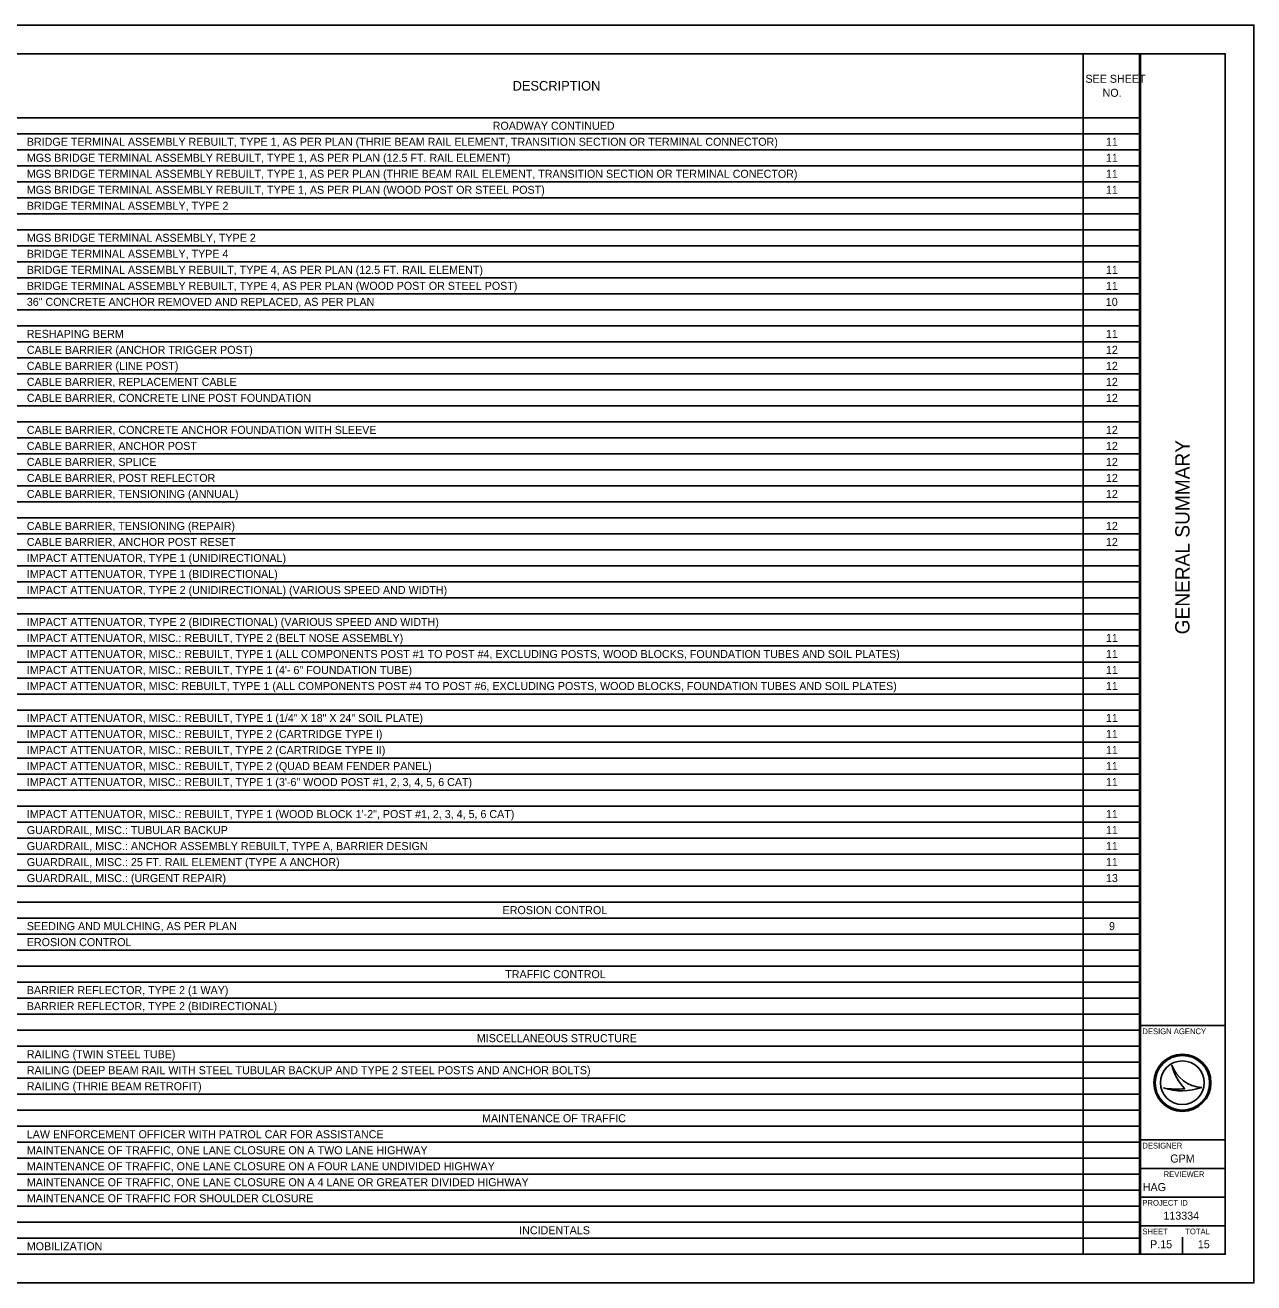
# Model space of a CAD drawing. Extents: x 0 to 34, y 0 to 22.
# Drawn here: x 12.51 to 34, y 0 to 22 of the extents above; entities that cross this region are included whole.
import ezdxf

# ---------------------------------------------------------------- set-up
doc = ezdxf.new("R2010")
doc.units = 0
for name, color, linetype in [('Default', 7, 'Continuous'), ('SH_Border', 7, 'Continuous'), ('SH_Cut_Line', 7, 'Continuous'), ('SH_Data', 7, 'Continuous')]:
    doc.layers.add(name, color=color, linetype=linetype)

msp = doc.modelspace()

# ---------------------------------------------------------------- linework, layer by layer
at = {"layer": 'Default'}
for p, q in [((1.5, 21.5), (32.02, 21.5)), ((31.015, 21.5), (31.015, 0.5)), ((32.02, 21.5), (32.02, 0.5)), ((1.5, 20.38), (32.02, 20.38)), ((1.5, 20.1), (32.02, 20.1)), ((1.5, 19.82), (32.02, 19.82)), ((1.5, 19.54), (32.02, 19.54)), ((1.5, 19.26), (32.02, 19.26)), ((1.5, 18.98), (32.02, 18.98)), ((1.5, 18.7), (32.02, 18.7)), ((1.5, 18.42), (32.02, 18.42)), ((1.5, 18.14), (32.02, 18.14)), ((1.5, 17.86), (32.02, 17.86)), ((1.5, 17.58), (32.02, 17.58)), ((1.5, 17.3), (32.02, 17.3)), ((1.5, 17.02), (32.02, 17.02)), ((1.5, 16.74), (32.02, 16.74)), ((1.5, 16.46), (32.02, 16.46)), ((1.5, 16.18), (32.02, 16.18)), ((1.5, 15.9), (32.02, 15.9)), ((1.5, 15.62), (32.02, 15.62)), ((1.5, 15.34), (32.02, 15.34)), ((1.5, 15.06), (32.02, 15.06)), ((1.5, 14.78), (32.02, 14.78)), ((1.5, 14.5), (32.02, 14.5)), ((1.5, 14.22), (32.02, 14.22)), ((1.5, 13.94), (32.02, 13.94)), ((1.5, 13.66), (32.02, 13.66)), ((1.5, 13.38), (32.02, 13.38)), ((1.5, 13.1), (32.02, 13.1)), ((1.5, 12.82), (32.02, 12.82)), ((1.5, 12.54), (32.02, 12.54)), ((1.5, 12.26), (32.02, 12.26)), ((1.5, 11.98), (32.02, 11.98)), ((1.5, 11.7), (32.02, 11.7)), ((1.5, 11.42), (32.02, 11.42)), ((1.5, 11.14), (32.02, 11.14)), ((1.5, 10.86), (32.02, 10.86)), ((1.5, 10.58), (32.02, 10.58)), ((1.5, 10.3), (32.02, 10.3)), ((1.5, 10.02), (32.02, 10.02)), ((1.5, 9.74), (32.02, 9.74)), ((1.5, 9.46), (32.02, 9.46)), ((1.5, 9.18), (32.02, 9.18)), ((1.5, 8.9), (32.02, 8.9)), ((1.5, 8.62), (32.02, 8.62)), ((1.5, 8.34), (32.02, 8.34)), ((1.5, 8.06), (32.02, 8.06)), ((1.5, 7.78), (32.02, 7.78)), ((1.5, 7.5), (32.02, 7.5)), ((1.5, 7.22), (32.02, 7.22)), ((1.5, 6.94), (32.02, 6.94)), ((1.5, 6.66), (32.02, 6.66)), ((1.5, 6.38), (32.02, 6.38)), ((1.5, 6.1), (32.02, 6.1)), ((1.5, 5.82), (32.02, 5.82)), ((1.5, 5.54), (32.02, 5.54)), ((1.5, 5.26), (32.02, 5.26)), ((1.5, 4.98), (32.02, 4.98)), ((1.5, 4.7), (32.02, 4.7)), ((1.5, 4.42), (32.02, 4.42)), ((1.5, 4.14), (32.02, 4.14)), ((1.5, 3.86), (32.02, 3.86)), ((1.5, 3.58), (32.02, 3.58)), ((1.5, 3.3), (32.02, 3.3)), ((1.5, 3.02), (32.02, 3.02)), ((1.5, 2.74), (32.02, 2.74)), ((1.5, 2.46), (32.02, 2.46)), ((1.5, 2.18), (32.02, 2.18)), ((1.5, 1.9), (32.02, 1.9)), ((1.5, 1.62), (32.02, 1.62)), ((1.5, 1.34), (32.02, 1.34)), ((1.5, 1.06), (32.02, 1.06)), ((1.5, 0.78), (32.02, 0.78)), ((1.5, 0.5), (32.02, 0.5))]:
    msp.add_line(p, q, dxfattribs=at)
at = {"layer": 'SH_Border'}
for p, q in [((32, 0.5), (32, 21.5)), ((32, 4.5), (33.5, 4.5)), ((32, 2.5), (33.5, 2.5)), ((32, 2), (33.5, 2)), ((32, 1.5), (33.5, 1.5)), ((32, 1), (33.5, 1))]:
    msp.add_line(p, q, dxfattribs=at)
msp.add_lwpolyline([(1.5, 21.5), (33.5, 21.5), (33.5, 0.5), (1.5, 0.5)], close=True, dxfattribs=at)
at = {"layer": 'SH_Cut_Line'}
msp.add_lwpolyline([(0, 0), (34, 0), (34, 22), (0, 22)], close=True, dxfattribs=at)
at = {"layer": 'SH_Data'}
for p, q in [((32.567, 3.81), (32.567, 3.81)), ((32.417, 3.41), (32.417, 3.41)), ((32.75, 3.5), (32.75, 3.5)), ((33.087, 3.419), (33.087, 3.419)), ((32.375, 0.675), (32.375, 0.675)), ((32.75, 0.5), (32.75, 0.8))]:
    msp.add_line(p, q, dxfattribs=at)
for radius in [0.5, 0.477, 0.477, 0.382]:
    msp.add_circle((32.75, 3.5), radius, dxfattribs=at)
for centre, radius, start, end in [((33.116, 3.998), 0.58, 198.9257, 198.9319), ((33.347, 3.97), 0.796, 191.6379, 191.6421), ((33.116, 3.998), 0.58, 198.9319, 267.1657), ((33.347, 3.97), 0.796, 191.6421, 226.0947), ((32.739, 4.37), 1.013, 251.4576, 290.0832), ((32.648, 4.654), 1.266, 259.4964, 259.4995), ((32.739, 4.37), 1.013, 251.4527, 251.4576), ((32.648, 4.654), 1.266, 259.4995, 276.6672)]:
    msp.add_arc(centre, radius, start, end, dxfattribs=at)

# ---------------------------------------------------------------- texts
at = {"layer": 'Default'}
for s, height, p in [('SEE SHEET ', 0.14, (31.054, 20.992)), ('DESCRIPTION', 0.168, (21.033, 20.856)), ('NO.', 0.14, (31.354, 20.747)), ('ROADWAY CONTINUED', 0.14, (20.685, 20.17)), ('BRIDGE TERMINAL ASSEMBLY REBUILT, TYPE 1, AS PER PLAN (THRIE BEAM RAIL ELEMENT, TRANSITION SECTION OR TERMINAL CONNECTOR)', 0.14, (12.535, 19.89)), ('11', 0.14, (31.412, 19.89)), ('MGS BRIDGE TERMINAL ASSEMBLY REBUILT, TYPE 1, AS PER PLAN (12.5 FT. RAIL ELEMENT)', 0.14, (12.535, 19.61)), ('11', 0.14, (31.412, 19.61)), ('MGS BRIDGE TERMINAL ASSEMBLY REBUILT, TYPE 1, AS PER PLAN (THRIE BEAM RAIL ELEMENT, TRANSITION SECTION OR TERMINAL CONECTOR)', 0.14, (12.535, 19.33)), ('11', 0.14, (31.412, 19.33)), ('MGS BRIDGE TERMINAL ASSEMBLY REBUILT, TYPE 1, AS PER PLAN (WOOD POST OR STEEL POST)', 0.14, (12.535, 19.05)), ('11', 0.14, (31.412, 19.05)), ('BRIDGE TERMINAL ASSEMBLY, TYPE 2', 0.14, (12.535, 18.77)), ('MGS BRIDGE TERMINAL ASSEMBLY, TYPE 2', 0.14, (12.535, 18.21)), ('BRIDGE TERMINAL ASSEMBLY, TYPE 4', 0.14, (12.535, 17.93)), ('BRIDGE TERMINAL ASSEMBLY REBUILT, TYPE 4, AS PER PLAN (12.5 FT. RAIL ELEMENT)', 0.14, (12.535, 17.65)), ('11', 0.14, (31.412, 17.65)), ('BRIDGE TERMINAL ASSEMBLY REBUILT, TYPE 4, AS PER PLAN (WOOD POST OR STEEL POST)', 0.14, (12.535, 17.37)), ('11', 0.14, (31.412, 17.37)), ('36" CONCRETE ANCHOR REMOVED AND REPLACED, AS PER PLAN', 0.14, (12.535, 17.09)), ('10', 0.14, (31.41, 17.09)), ('RESHAPING BERM', 0.14, (12.535, 16.53)), ('11', 0.14, (31.412, 16.53)), ('CABLE BARRIER (ANCHOR TRIGGER POST)', 0.14, (12.535, 16.25)), ('12', 0.14, (31.412, 16.25)), ('CABLE BARRIER (LINE POST)', 0.14, (12.535, 15.97)), ('12', 0.14, (31.412, 15.97)), ('CABLE BARRIER, REPLACEMENT CABLE', 0.14, (12.535, 15.69)), ('12', 0.14, (31.412, 15.69)), ('CABLE BARRIER, CONCRETE LINE POST FOUNDATION', 0.14, (12.535, 15.41)), ('12', 0.14, (31.412, 15.41)), ('CABLE BARRIER, CONCRETE ANCHOR FOUNDATION WITH SLEEVE', 0.14, (12.535, 14.85)), ('12', 0.14, (31.412, 14.85)), ('CABLE BARRIER, ANCHOR POST', 0.14, (12.535, 14.57)), ('12', 0.14, (31.412, 14.57)), ('CABLE BARRIER, SPLICE', 0.14, (12.535, 14.29)), ('12', 0.14, (31.412, 14.29)), ('CABLE BARRIER, POST REFLECTOR', 0.14, (12.535, 14.01)), ('12', 0.14, (31.412, 14.01)), ('CABLE BARRIER, TENSIONING (ANNUAL)', 0.14, (12.535, 13.73)), ('12', 0.14, (31.412, 13.73)), ('CABLE BARRIER, TENSIONING (REPAIR)', 0.14, (12.535, 13.17)), ('12', 0.14, (31.412, 13.17)), ('CABLE BARRIER, ANCHOR POST RESET', 0.14, (12.535, 12.89)), ('12', 0.14, (31.412, 12.89)), ('IMPACT ATTENUATOR, TYPE 1 (UNIDIRECTIONAL)', 0.14, (12.535, 12.61)), ('IMPACT ATTENUATOR, TYPE 1 (BIDIRECTIONAL)', 0.14, (12.535, 12.33)), ('IMPACT ATTENUATOR, TYPE 2 (UNIDIRECTIONAL) (VARIOUS SPEED AND WIDTH)', 0.14, (12.535, 12.05)), ('IMPACT ATTENUATOR, TYPE 2 (BIDIRECTIONAL) (VARIOUS SPEED AND WIDTH)', 0.14, (12.535, 11.49)), ('IMPACT ATTENUATOR, MISC.: REBUILT, TYPE 2 (BELT NOSE ASSEMBLY)', 0.14, (12.535, 11.21)), ('11', 0.14, (31.412, 11.21)), ('IMPACT ATTENUATOR, MISC.: REBUILT, TYPE 1 (ALL COMPONENTS POST #1 TO POST #4, EXCLUDING POSTS, WOOD BLOCKS, FOUNDATION TUBES AND SOIL PLATES)', 0.14, (12.535, 10.93)), ('11', 0.14, (31.412, 10.93)), ('IMPACT ATTENUATOR, MISC.: REBUILT, TYPE 1 (4\'- 6" FOUNDATION TUBE)', 0.14, (12.535, 10.65)), ('11', 0.14, (31.412, 10.65)), ('IMPACT ATTENUATOR, MISC: REBUILT, TYPE 1 (ALL COMPONENTS POST #4 TO POST #6, EXCLUDING POSTS, WOOD BLOCKS, FOUNDATION TUBES AND SOIL PLATES)', 0.14, (12.535, 10.37)), ('11', 0.14, (31.412, 10.37)), ('IMPACT ATTENUATOR, MISC.: REBUILT, TYPE 1 (1/4" X 18" X 24" SOIL PLATE)', 0.14, (12.535, 9.81)), ('11', 0.14, (31.412, 9.81)), ('IMPACT ATTENUATOR, MISC.: REBUILT, TYPE 2 (CARTRIDGE TYPE I)', 0.14, (12.535, 9.53)), ('11', 0.14, (31.412, 9.53)), ('IMPACT ATTENUATOR, MISC.: REBUILT, TYPE 2 (CARTRIDGE TYPE II)', 0.14, (12.535, 9.25)), ('11', 0.14, (31.412, 9.25)), ('IMPACT ATTENUATOR, MISC.: REBUILT, TYPE 2 (QUAD BEAM FENDER PANEL)', 0.14, (12.535, 8.97)), ('11', 0.14, (31.412, 8.97)), ('IMPACT ATTENUATOR, MISC.: REBUILT, TYPE 1 (3\'-6" WOOD POST #1, 2, 3, 4, 5, 6 CAT)', 0.14, (12.535, 8.69)), ('11', 0.14, (31.412, 8.69)), ('IMPACT ATTENUATOR, MISC.: REBUILT, TYPE 1 (WOOD BLOCK 1\'-2", POST #1, 2, 3, 4, 5, 6 CAT)', 0.14, (12.535, 8.13)), ('11', 0.14, (31.412, 8.13)), ('GUARDRAIL, MISC.: TUBULAR BACKUP', 0.14, (12.535, 7.85)), ('11', 0.14, (31.412, 7.85)), ('GUARDRAIL, MISC.: ANCHOR ASSEMBLY REBUILT, TYPE A, BARRIER DESIGN', 0.14, (12.535, 7.57)), ('11', 0.14, (31.412, 7.57)), ('GUARDRAIL, MISC.: 25 FT. RAIL ELEMENT (TYPE A ANCHOR)', 0.14, (12.535, 7.29)), ('11', 0.14, (31.412, 7.29)), ('GUARDRAIL, MISC.: (URGENT REPAIR)', 0.14, (12.535, 7.01)), ('13', 0.14, (31.413, 7.01)), ('EROSION CONTROL', 0.14, (20.858, 6.45)), ('SEEDING AND MULCHING, AS PER PLAN', 0.14, (12.535, 6.17)), ('9', 0.14, (31.467, 6.17)), ('EROSION CONTROL', 0.14, (12.535, 5.89)), ('TRAFFIC CONTROL', 0.14, (20.904, 5.33)), ('BARRIER REFLECTOR, TYPE 2 (1 WAY)', 0.14, (12.535, 5.05)), ('BARRIER REFLECTOR, TYPE 2 (BIDIRECTIONAL)', 0.14, (12.535, 4.77)), ('MISCELLANEOUS STRUCTURE', 0.14, (20.408, 4.21)), ('RAILING (TWIN STEEL TUBE)', 0.14, (12.535, 3.93)), ('RAILING (DEEP BEAM RAIL WITH STEEL TUBULAR BACKUP AND TYPE 2 STEEL POSTS AND ANCHOR BOLTS)', 0.14, (12.535, 3.65)), ('RAILING (THRIE BEAM RETROFIT)', 0.14, (12.535, 3.37)), ('MAINTENANCE OF TRAFFIC', 0.14, (20.499, 2.81)), ('LAW ENFORCEMENT OFFICER WITH PATROL CAR FOR ASSISTANCE', 0.14, (12.535, 2.53)), ('MAINTENANCE OF TRAFFIC, ONE LANE CLOSURE ON A TWO LANE HIGHWAY', 0.14, (12.535, 2.25)), ('MAINTENANCE OF TRAFFIC, ONE LANE CLOSURE ON A FOUR LANE UNDIVIDED HIGHWAY', 0.14, (12.535, 1.97)), ('MAINTENANCE OF TRAFFIC, ONE LANE CLOSURE ON A 4 LANE OR GREATER DIVIDED HIGHWAY', 0.14, (12.535, 1.69)), ('MAINTENANCE OF TRAFFIC FOR SHOULDER CLOSURE', 0.14, (12.535, 1.41)), ('INCIDENTALS', 0.14, (21.148, 0.85)), ('MOBILIZATION', 0.14, (12.535, 0.57))]:
    msp.add_text(s, height=height, dxfattribs=at).set_placement(p)
at = {"layer": 'SH_Data'}
msp.add_text('GENERAL SUMMARY', height=0.25, rotation=90, dxfattribs=at).set_placement((32.875, 11.344))
for s, height, p in [('DESIGN AGENCY', 0.1, (32.05, 4.35)), ('DESIGNER', 0.1, (32.05, 2.35)), ('GPM', 0.14, (32.538, 2.105)), ('REVIEWER', 0.1, (32.422, 1.85)), ('HAG', 0.14, (32.057, 1.605)), ('PROJECT ID', 0.1, (32.05, 1.35)), ('113334', 0.14, (32.418, 1.105)), ('SHEET', 0.1, (32.05, 0.85)), ('TOTAL', 0.1, (32.8, 0.85)), ('P.15', 0.14, (32.185, 0.605)), ('15', 0.14, (33.02, 0.605))]:
    msp.add_text(s, height=height, dxfattribs=at).set_placement(p)

doc.saveas('drawing.dxf')
